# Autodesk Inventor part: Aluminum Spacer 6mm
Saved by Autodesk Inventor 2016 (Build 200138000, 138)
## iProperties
Created: 2016-03
Part Number: Aluminum Spacer 6mm
Material: Generic
Document SubType Name: Modeling
Designer: bongo_000
Density: 1 g/cm^3
Appearance: Default
Author: bongo_000
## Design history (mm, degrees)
feature "CHAMFER1"
body "Solid1"
